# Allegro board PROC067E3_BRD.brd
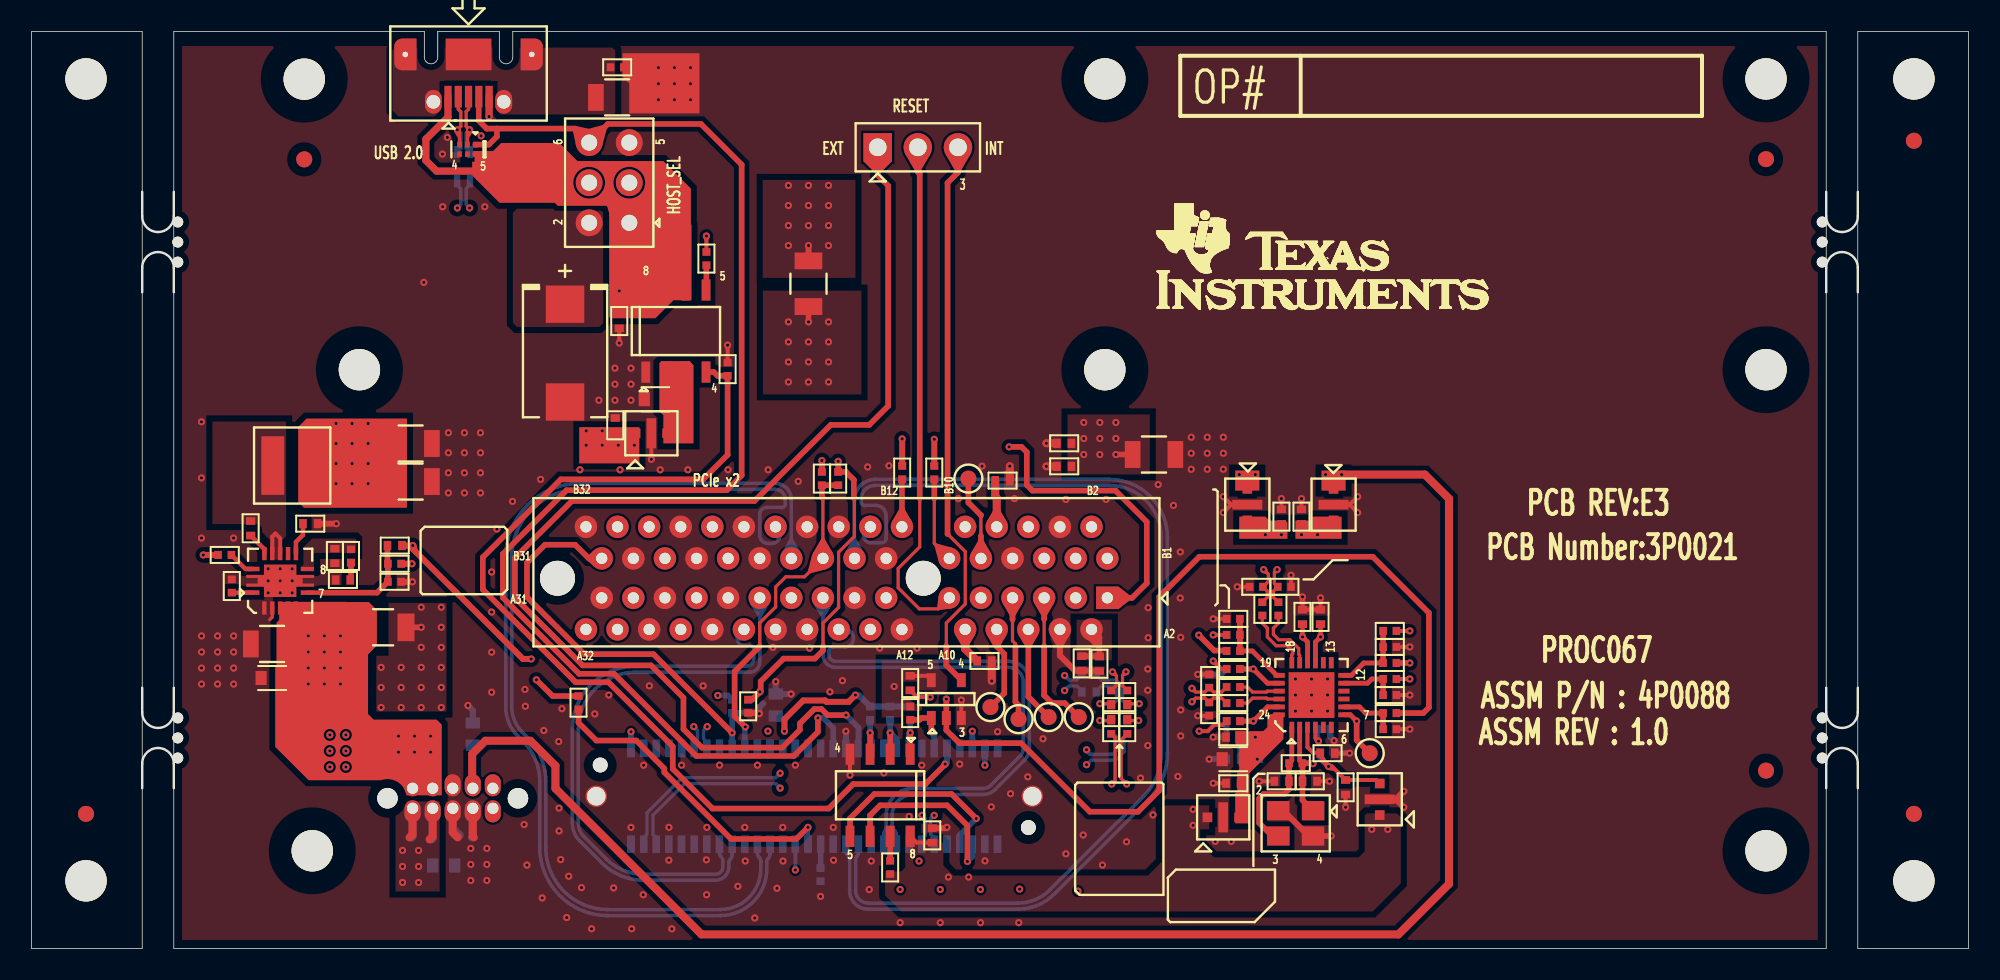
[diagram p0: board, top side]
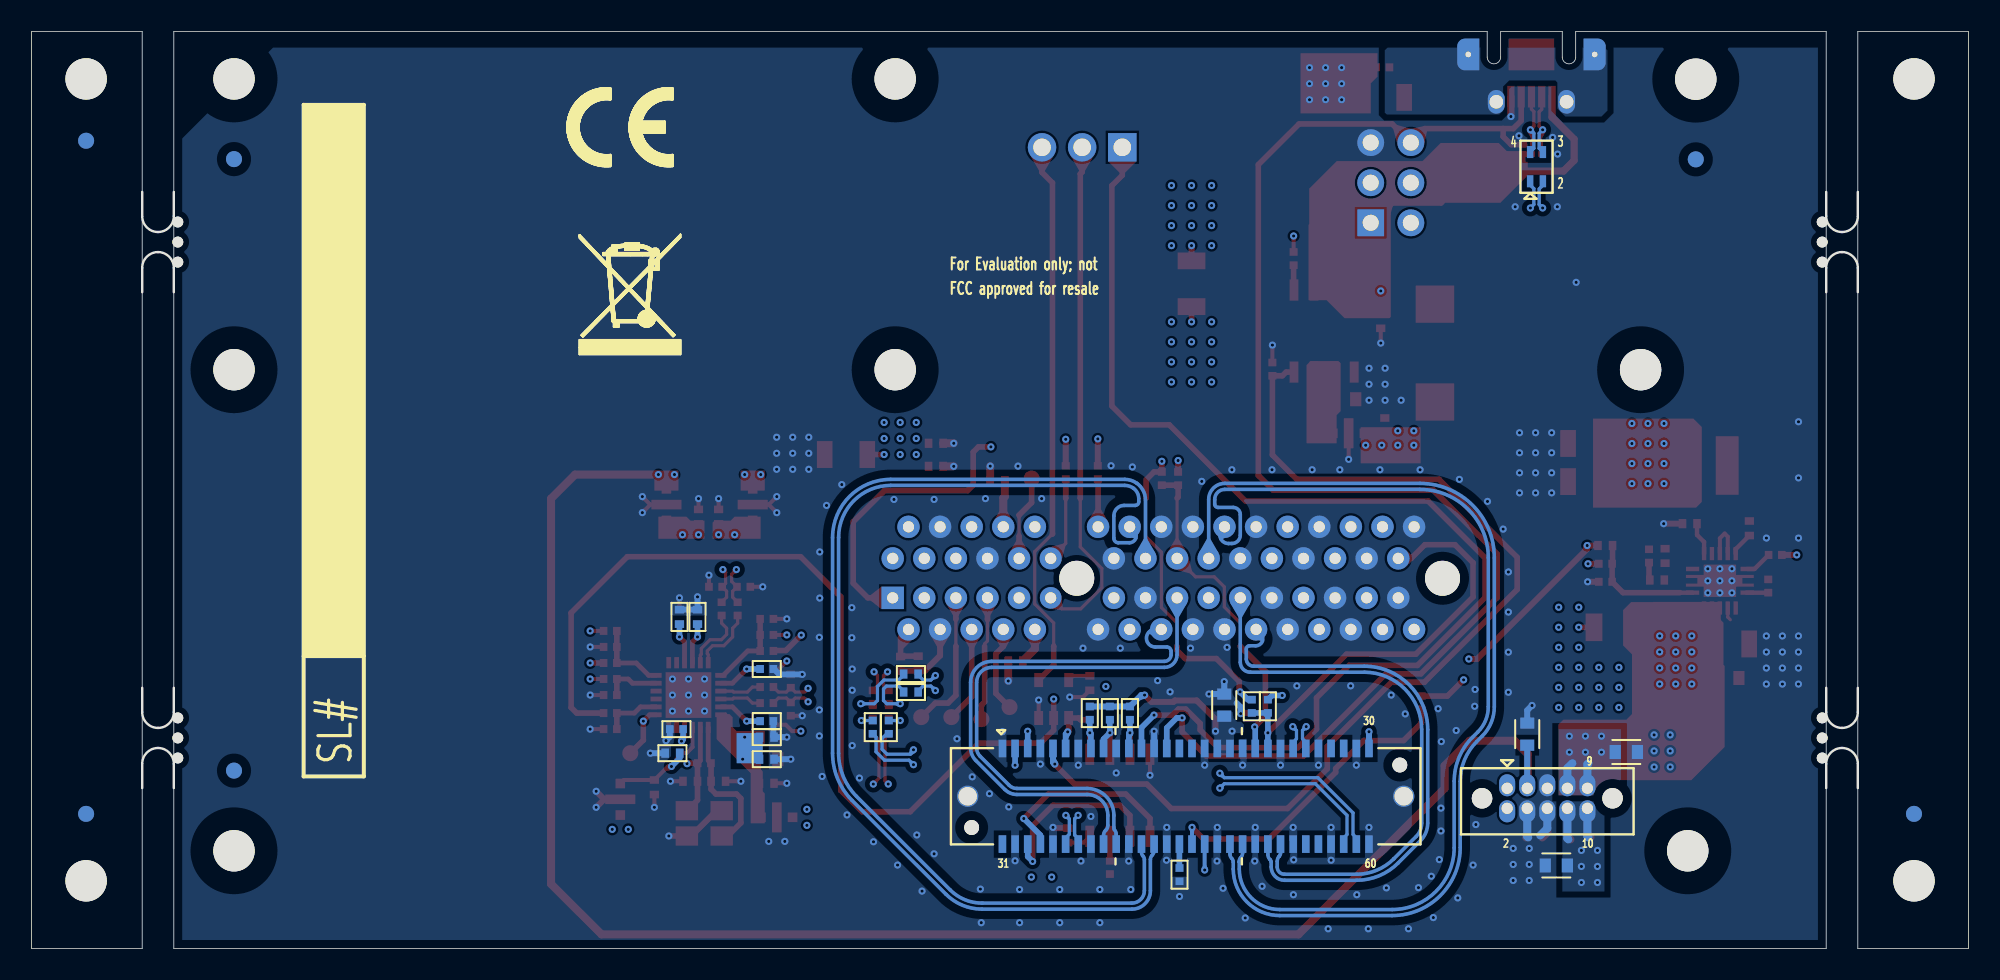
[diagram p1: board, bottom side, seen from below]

Outline 122.58 x 58.09 mm; copper layers: TOP, L02_GND1, L03_PWR, L04_SIG1, L05_GND2, BOTTOM. Coordinates in mm from the lower left corner of the outline.
Outline path: 0,58.09 7,58.09 7,0 0,0 0,58.09 ; 9,58.09 9,0 113.58,0 113.58,58.09 30.46,58.09 30.46,56.47 arc(30.03,56.05) 29.61,56.47 29.61,58.09 25.71,58.09 25.71,56.47 arc(25.28,56.05) 24.86,56.47 24.86,58.09 9,58.09 ; 115.58,58.09 122.58,58.09 122.58,0 115.58,0 115.58,58.09

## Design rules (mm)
net group 4_REFCLK_OUT0N: nets 4_REFCLK_OUT0N N17084031
net group 4_REFCLK_OUT0P: nets 4_REFCLK_OUT0P N17084018
net group DIFF_4_CLKGEN_REFCLK1: nets 4_CLKGEN_REFCLK1N 4_CLKGEN_REFCLK1P
net group DIFF_4_CLKGEN_REFCLK2: nets 4_CLKGEN_REFCLK2N 4_CLKGEN_REFCLK2P
net group DIFF_4_PCIE_REFCLK: nets 4_PCIE_REFCLK_N 4_PCIE_REFCLK_P
net group DIFF_4_REFCLK_IN0: nets 4_REFCLK_IN0N 4_REFCLK_IN0P
net group DIFF_4_USB_CM_D: nets 4_USB_CM_DM 4_USB_CM_DP
net group DIFF_4_USB_D: nets 4_USB_DM 4_USB_DP
net group DIFF_CDCI4_Y1: nets CDCI4_Y1N CDCI4_Y1P
net group DIFF_CDCI4_Y2: nets CDCI4_Y2N CDCI4_Y2P

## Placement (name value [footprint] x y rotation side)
C127  1000pF  [CAP1206]  37.06 53.92 180 top
C128  4.7uF  [CAP0402_0-75]  37.19 39.75 270 top
C129  150uF_10V  [CAPT7343D_3-25]  33.76 37.72 270 top
C130  10uF  [CAP0603_1]  39.48 34.8 180 top
C131  0.1uF  [CAP0402_0-75]  36.94 33.15 90 top
C132  0.01uF  [CAP0402]  65.35 32 180 top
C133  47uF  [CAP1206_2]  23.99 31.99 0 top
C134  47uF  [CAP1206_2]  71.04 31.29 0 top
C135  0.1uF  [CAP0402_0-75]  65.36 30.54 180 top
C136  0.1uF  [CAP0402_0-75]  61.45 29.64 0 top
C137  47uF  [CAP1206_2]  23.99 29.58 0 top
C138  4.7uF  [CAP0402_0-75]  79.1 27.36 90 top
C139  4.7uF  [CAP0402_0-75]  80.37 27.36 90 top
C140  0.01uF  [CAP0402]  17.64 26.91 0 top
C141  0.1uF  [CAP0402_0-75]  13.86 26.62 270 top
C142  510pF  [CAP0402]  22.98 25.53 180 top
C143  91pF  [CAP0402]  19.2 24.87 270 top
C144  1500pF  [CAP0402]  19.71 23.34 180 top
C145  0.1uF  [CAP0402_0-75]  80.44 21.01 270 top
C146  0.1uF  [CAP0402_0-75]  81.58 21.01 270 top
C147  4.7uF  [CAP1206]  15.22 19.29 180 top
C148  0.01uF  [CAP0402]  60.31 18.21 0 top
C149  0.01uF  [CAP0402]  66.47 18.06 270 top
C150  10uF  [CAP0603_1]  15.22 17.13 180 top
C151  0.1uF  [CAP0402_0-75]  55.61 16.81 270 top
C152  0.1uF  [CAP0402_0-75]  67.59 18.03 270 top
C153  0.1uF  [CAP0402_0-75]  76.06 13.39 0 top
C154  0.1uF  [CAP0402_0-75]  82.02 12.37 180 top
C155  10uF  [CAP0603_1]  76.06 11.99 180 top
C156  27pF  [CAP0402]  79.12 10.59 0 top
C157  27pF  [CAP0402]  80.9 10.59 180 top
C158  4.7uF  [CAP0402_0-75]  76.06 10.46 180 top
C159  0.47uF  [CAP0402_0-75]  83.17 10.21 270 top
C160  0.1uF  [CAP0402_0-75]  57.01 7.16 90 top
C221  0.47uF  [CAP0402_0-75]  81.58 21.01 90 bottom
C222  0.47uF  [CAP0402_0-75]  80.44 21.01 90 bottom
C223  0.1uF  [CAP0402_0-75]  66.93 17.39 180 bottom
C224  0.1uF  [CAP0402_0-75]  66.93 16.24 180 bottom
C225  10uF  [CAP0603_1]  47.1 15.42 90 bottom
C226  10uF  [CAP0603_1]  27.92 13.58 90 bottom
C227  0.47uF  [CAP0402_0-75]  76.06 13.39 180 bottom
C228  10uF  [CAP0603_1]  21.65 12.45 180 bottom
C229  4.7uF  [CAP0402_0-75]  82.02 12.37 0 bottom
C230  1uF  [CAP0402]  76.06 11.99 0 bottom
C231  10uF  [CAP0603_1]  26.08 5.26 0 bottom
FL16  4.7uF  [EMIFIL_NFM21P_0805_1]  39.23 32.64 0 top
FL17  0.47uF  [EMIFIL_NFM21P_0805]  76.94 28.12 270 top
FL18  0.47uF  [EMIFIL_NFM21P_0805]  82.41 28.12 270 top
FL19  0.47uF  [EMIFIL_NFM21P_0805]  85.33 9.45 90 top
FL20  0.47uF  [EMIFIL_NFM21P_0805]  75.42 8.31 0 top
FL25  90E  [IND4_ACM2012_90X50_SMD]  27.34 49.53 90 bottom
J5  HDR_2X3  [HDR_2X3_TSW-103-07-D_S_T_8-4]  37.83 45.97 90 top
J13  CON_MUSB-AB_5_F  [CON_USBAB5_475900001_S_R_S_3-1]  27.66 56 180 top
J14  HDR_1X3  [HDR_3X1_100_S_T]  53.55 50.76 180 top
J15  CON_MINIPCI_2X32  [CON_MINIPCI2X32_PCIE-064-02_S_S_T_11]  68.08 22.21 180 top
J22  CON_BTOB_2X30_171450_F  [CON_BTOB2X30_171450_S_S_S_4-6]  49.54 9.64 180 bottom
J23  RECP_2X5  [RECPT_2X5_SFC-105-T1-D-A_S_T_4-6]  29.19 10.15 180 bottom
L3  1uH  [IND_XFL4020_170X170_SMD_2-1]  16.49 30.59 0 top
NOREF  -  [unnamed]  17.25 55.07 0 top
NOREF#2  -  [#2]  122.58 0 90 top
NOREF#3  -  [unnamed#3]  114.58 44.75 90 top
NOREF#4  -  [unnamed]  67.93 36.67 0 top
NOREF#5  -  [unnamed]  119.14 4.28 0 top
NOREF#6  -  [unnamed]  3.44 8.52 0 top
NOREF#7  -  [#2]  7 58.09 0 top
NOREF#8  -  [unnamed]  109.77 55.09 0 top
NOREF#9  -  [#2]  86.93 38.98 0 top
NOREF#10  -  [#2]  0 58.09 0 top
NOREF#11  -  [unnamed#3]  8 44.75 270 top
NOREF#12  -  [unnamed]  3.44 4.28 0 top
NOREF#13  -  [#2]  115.58 58.09 0 top
NOREF#14  -  [#2]  63.38 51.68 0 top
NOREF#15  -  [unnamed]  119.14 51.17 0 top
NOREF#16  -  [unnamed]  109.77 6.19 0 top
NOREF#17  -  [unnamed]  109.77 11.27 0 top
NOREF#18  -  [#2]  -16.96 -24.57 0 top
NOREF#19  -  [unnamed]  119.14 55.09 0 top
NOREF#20  -  [#2]  -2.2 -4.94 0 top
NOREF#21  -  [unnamed]  17.76 6.19 0 top
NOREF#22  -  [unnamed]  3.44 55.09 0 top
NOREF#23  -  [#2]  -267.58 -119.24 0 top
NOREF#24  -  [#2]  90.84 34.74 0 top
NOREF#25  -  [unnamed]  17.25 49.99 0 top
NOREF#26  -  [unnamed]  20.75 36.67 0 top
NOREF#27  -  [unnamed]  109.77 50.01 0 top
NOREF#28  -  [#2]  0 0 0 top
NOREF#29  -  [unnamed#3]  114.58 13.34 90 top
NOREF#30  -  [unnamed]  119.14 8.52 0 top
NOREF#31  -  [unnamed]  67.93 55.09 0 top
NOREF#32  -  [unnamed#3]  8 13.34 270 top
NOREF#33  -  [unnamed]  109.77 36.67 0 top
NOREF#34  -  [unnamed]  3.44 8.52 180 bottom
NOREF#35  -  [#2]  86.17 52.04 180 bottom
NOREF#36  -  [#2]  105.37 10.9 90 bottom
NOREF#37  -  [unnamed]  109.77 50.01 180 bottom
NOREF#38  -  [unnamed]  119.14 51.17 180 bottom
NOREF#39  -  [unnamed]  109.77 11.27 180 bottom
NOREF#40  -  [unnamed]  119.14 8.52 180 bottom
NOREF#41  -  [unnamed]  17.25 49.99 180 bottom
R211  1M_1%  [RES0402]  37.06 55.82 180 top
R212  10K_1%  [RES0402_0-5]  42.71 43.71 270 top
R213  0E_1%  [RES1206]  49.17 42.11 270 top
R214  10K_1%  [RES0402_0-5]  44.05 36.7 90 top
R215  10K_1%  [RES0402_0-5]  50.02 29.77 270 top
R216  0E  [RES0402_0-5]  51.05 29.77 90 top
R217  10K_1%  [RES0402_0-5]  55.1 30.15 270 top
R218  10K_1%  [RES0402_0-5]  57.13 30.15 270 top
R219  100K  [RES0402_0-5]  12.23 24.93 0 top
R220  1.96K_1%  [RES0402]  20.21 24.87 270 top
R221  10K_1%  [RES0402_0-5]  22.97 24.37 0 top
R222  2.2K  [RES0402_0-5]  22.97 23.23 0 top
R223  34K_1%  [RES0402]  12.67 22.96 90 top
R224  49.9E_1%  [RES0402_0-5]  77.52 22.91 180 top
R225  49.9E_1%  [RES0402_0-5]  79.29 22.91 0 top
R226  33E_1%  [RES0402_0-5]  77.9 21.51 90 top
R227  33E_1%  [RES0402_0-5]  78.91 21.51 90 top
R228  4.7K  [RES0402]  76.06 20.88 180 top
R229  0E_1%  [RES1206]  22.25 20.35 0 top
R230  4.7K  [RES0402]  85.96 20.12 180 top
R231  4.7K  [RES0402]  76.06 19.86 0 top
R232  4.7K  [RES0402]  85.96 19.1 0 top
R233  0E  [RES0402_0-5]  76.06 18.85 0 top
R234  0E  [RES0402_0-5]  85.96 18.08 180 top
R235  4.7K  [RES0402]  76.06 17.7 0 top
R236  4.7K  [RES0402]  85.96 17.07 180 top
R237  49.9E_1%  [RES0402_0-5]  74.53 16.94 90 top
R238  33E_1%  [RES0402_0-5]  76.06 16.56 180 top
R239  4.7K  [RES0402]  85.96 16.05 0 top
R240  0E  [RES0402_0-5]  68.33 15.92 90 top
R241  0E  [RES0402_0-5]  69.35 15.92 90 top
R242  33E_1%  [RES0402_0-5]  76.06 15.54 180 top
R243  0E  [RES0402_0-5]  45.35 15.34 90 top
R244  49.9E_1%  [RES0402_0-5]  74.53 15.16 270 top
R245  0E  [RES0402_0-5]  68.33 14.97 270 top
R246  0E  [RES0402_0-5]  69.35 14.97 270 top
R247  10K_1%  [RES0402_0-5]  55.61 14.91 90 top
R248  0E  [RES0402_0-5]  85.96 14.91 180 top
R250  1K  [RES0402_0-5]  76.06 14.4 0 top
R251  0E  [RES0402_0-5]  68.33 14.02 270 top
R252  0E  [RES0402_0-5]  69.35 14.02 270 top
R253  4.7K  [RES0402]  85.96 13.89 0 top
R254  1M_1%  [RES0402]  80.01 11.73 0 top
R255  10K_1%  [RES0402_0-5]  54.34 5.13 90 top
R297  4.7K  [RES0402]  76.06 17.7 180 bottom
R298  0E  [RES0402_0-5]  45.35 15.34 90 bottom
R299  10K_1%  [RES0402_0-5]  44.34 15.34 270 bottom
R300  10K_1%  [RES0402_0-5]  55.61 14.91 270 bottom
R301  10K_1%  [RES0402_0-5]  54.34 14.91 270 bottom
R302  10K_1%  [RES0402_0-5]  53.07 14.91 270 bottom
R304  1K  [RES0402_0-5]  76.06 14.4 180 bottom
R305  0E  [RES0402_0-5]  69.35 14.02 270 bottom
R306  0E  [RES0402_0-5]  68.33 14.02 270 bottom
R307  4.7K  [RES0402]  81.77 13.89 0 bottom
R308  0E  [RES0402_0-5]  49.93 4.67 270 bottom
R311  0E  [RES0402_0-5]  34.62 15.57 90 top
TP22  -  [TP40_SMD]  59.29 29.77 0 top
TP23  -  [TP40_SMD]  60.69 15.29 0 top
TP24  -  [TP40_SMD]  64.37 14.66 0 top
TP25  -  [TP40_SMD]  66.28 14.66 0 top
TP26  -  [TP40_SMD]  62.47 14.53 0 top
TP27  -  [TP40_SMD]  84.69 12.37 270 top
U20  TPD4S012DRYR  [SON6_19-68_40X60_PB_0-6]  27.59 50.63 270 top
U21  TPS2051BD  [SOIC8_1-8]  40.78 39.12 90 top
U22  TPS54821RHLT  [QFN14_19-68_145X145]  15.73 23.29 0 top
U23  CDCI6214RGET  [QFN24_19-68_160X160_1]  81.01 16.05 90 top
U24  SN74LVC1G08DBVRE4  [SOT23-5]  57.89 15.8 90 top
U25  CAT24C256WI-GT3  [SOIC8_1-8]  53.7 9.7 270 top
Y6  25.000MHz  [XTAL4_NX3225GA_130X100_SMD]  80.01 7.92 180 top

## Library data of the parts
C127 C128 C130-C160 C221 C222 C225-C231 = CAP
C129 = CAP_POL
C223 C224 = CAP: signal model: cap
FL16 = EMI_FILTER
FL17-FL20 = CAP_FILTER
FL25 = EMIFILTER_ACM
J5 = HEADER_3X2
J13 = CON_USB_MINI-AB_10
J14 = HEADER_3X1
J15 = CON_MINIPCI_32X2
J22 = CON_BTOB_30X2_171450
J23 = RECP_5X2
L3 = INDUCTOR
R211-R248 R250-R255 R297-R302 R304-R308 R311 = RESISTOR
TP22-TP27 = TESTPOINT
U20 = TPD4S012DRY_SON6
U21 = TPS2051BD_SOIC8
U22 = TPS54620_QFN14
U23 = CDCI6214RGET_VQFN24
U24 = SN74LVC1G08DBVRE4_SOT23-5
U25 = CAT24C256WI-GT3_SOIC8
Y6 = CRY_CX3225GB

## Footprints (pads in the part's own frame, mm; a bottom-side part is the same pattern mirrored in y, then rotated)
CAP0402
  rect 0.483x0.584 smd: 1(-0.46,0) 2(0.46,0)
CAP0402_0-75
  rect 0.483x0.584 smd: 1(-0.46,0) 2(0.46,0)
CAP0603_1
  rect 0.711x0.889 smd: 1(-0.7,0) 2(0.7,0)
CAP1206
  rect 0.991x1.702 smd: 1(-1.35,0) 2(1.35,0)
CAP1206_2
  rect 0.991x1.702 smd: 1(-1.35,0) 2(1.35,0)
CAPT7343D_3-25
  rect 2.362x2.438 smd: 1(-3.1,0) 2(3.1,0)
CON_BTOB2X30_171450_S_S_S_4-6
  round 0.94 hole 1.067 unplated: (-13.55,-1.98) (13.55,1.98)
  rect 0.483x1.118 smd: 1(-11.6,3.03) 2(-10.8,3.03) 3(-10,3.03) 4(-9.2,3.03) 5(-8.4,3.03) 6(-7.6,3.03) 7(-6.8,3.03) 8(-6,3.03) 9(-5.2,3.03) 10(-4.4,3.03) 11(-3.6,3.03) 12(-2.8,3.03) 13(-2,3.03) 14(-1.2,3.03) 15(-0.4,3.03) 16(0.4,3.03) 17(1.2,3.03) 18(2,3.03) 19(2.8,3.03) 20(3.6,3.03) 21(4.4,3.03) 22(5.2,3.03) 23(6,3.03) 24(6.8,3.03) 25(7.6,3.03) 26(8.4,3.03) 27(9.2,3.03) 28(10,3.03) 29(10.8,3.03) 30(11.6,3.03) 31(-11.6,-3.03) 32(-10.8,-3.03) 33(-10,-3.03) 34(-9.2,-3.03) 35(-8.4,-3.03) 36(-7.6,-3.03) 37(-6.8,-3.03) 38(-6,-3.03) 39(-5.2,-3.03) 40(-4.4,-3.03) 41(-3.6,-3.03) 42(-2.8,-3.03) 43(-2,-3.03) 44(-1.2,-3.03) 45(-0.4,-3.03) 46(0.4,-3.03) 47(1.2,-3.03) 48(2,-3.03) 49(2.8,-3.03) 50(3.6,-3.03) 51(4.4,-3.03) 52(5.2,-3.03) 53(6,-3.03) 54(6.8,-3.03) 55(7.6,-3.03) 56(8.4,-3.03) 57(9.2,-3.03) 58(10,-3.03) 59(10.8,-3.03) 60(11.6,-3.03)
  round 1.346 hole 1.168: SH1(-13.8,0) SH2(13.8,0)
CON_MINIPCI2X32_PCIE-064-02_S_S_T_11
  round 2.21 hole 2.337 unplated: (11.65,-1.24) (34.8,-1.24)
  rect 1.422x1.422 hole 0.711: A1(0,0)
  round 1.422 hole 0.711: A2(1,2) A3(2,0) A4(3,2) A5(4,0) A6(5,2) A7(6,0) A8(7,2) A9(8,0) A10(9,2) A12(13,2) A13(14,0) A14(15,2) A15(16,0) A16(17,2) A17(18,0) A18(19,2) A19(20,0) A20(21,2) A21(22,0) A22(23,2) A23(24,0) A24(25,2) A25(26,0) A26(27,2) A27(28,0) A28(29,2) A29(30,0) A30(31,2) A31(32,0) A32(33,2) B1(0,-2.5) B2(1,-4.5) B3(2,-2.5) B4(3,-4.5) B5(4,-2.5) B6(5,-4.5) B7(6,-2.5) B8(7,-4.5) B9(8,-2.5) B10(9,-4.5) B12(13,-4.5) B13(14,-2.5) B14(15,-4.5) B15(16,-2.5) B16(17,-4.5) B17(18,-2.5) B18(19,-4.5) B19(20,-2.5) B20(21,-4.5) B21(22,-2.5) B22(23,-4.5) B23(24,-2.5) B24(25,-4.5) B25(26,-2.5) B26(27,-4.5) B27(28,-2.5) B28(29,-4.5) B29(30,-2.5) B30(31,-4.5) B31(32,-2.5) B32(33,-4.5)
  round 1.372 hole 0.711: A11(10,0)
  round 1.397 hole 0.711: B11(10,-2.5)
CON_USBAB5_475900001_S_R_S_3-1
  rect 0.457x1.372 smd: 1(1.3,2.04) 2(0.65,2.04) 3(0,2.04) 4(-0.65,2.04) 5(-1.3,2.04)
  oval 1.067x1.499 hole 0.864: 6(2.225,2.365) 7(-2.225,2.365)
  custom 0.35x0.35 hole 0.813x1.626: 8(-4,-0.635) 9(4,-0.635)
  rect 2.896x2.007 smd: 10(0,-0.635)
EMIFIL_NFM21P_0805
  rect 0.61x0.61 smd: 1(-1,0) 3(1,0)
  rect 0.61x1.905 smd: 2(0,0)
EMIFIL_NFM21P_0805_1
  rect 0.61x0.61 smd: 1(-1,0) 3(1,0)
  rect 0.61x1.905 smd: 2(0,0)
HDR_2X3_TSW-103-07-D_S_T_8-4
  rect 1.702x1.702 hole 1.016: 1(0,0)
  round 1.702 hole 1.016: 2(0,2.54) 3(2.54,0) 4(2.54,2.54) 5(5.08,0) 6(5.08,2.54)
HDR_3X1_100_S_T
  rect 1.803x1.803 hole 1.118: 1(0,0)
  round 1.803 hole 1.118: 2(-2.54,0) 3(-5.08,0)
IND4_ACM2012_90X50_SMD
  rect 0.762x0.406 smd: 1(-0.925,0.403) 2(-0.925,-0.403) 3(0.925,-0.403) 4(0.925,0.403)
IND_XFL4020_170X170_SMD_2-1
  rect 1.448x3.708 smd: 1(-1.225,0) 2(1.225,0)
QFN14_19-68_145X145
  rect 0.838x0.279 smd: 1(-1.725,-0.75) 7(1.725,-0.75) 8(1.725,0.75) 14(-1.725,0.75)
  rect 0.279x0.838 smd: 2(-1,-1.725) 3(-0.5,-1.725) 4(0,-1.725) 5(0.5,-1.725) 6(1,-1.725) 9(1,1.725) 10(0.5,1.725) 11(0,1.725) 12(-0.5,1.725) 13(-1,1.725)
  custom 0.512x0.512 smd: 15(0,0)
QFN24_19-68_160X160_1
  rect 0.711x0.305 smd: 1(-2.05,1.25) 2(-2.05,0.75) 3(-2.05,0.25) 4(-2.05,-0.25) 5(-2.05,-0.75) 6(-2.05,-1.25) 13(2.05,-1.25) 14(2.05,-0.75) 15(2.05,-0.25) 16(2.05,0.25) 17(2.05,0.75) 18(2.05,1.25)
  rect 0.305x0.711 smd: 7(-1.25,-2.05) 8(-0.75,-2.05) 9(-0.25,-2.05) 10(0.25,-2.05) 11(0.75,-2.05) 12(1.25,-2.05) 19(1.25,2.05) 20(0.75,2.05) 21(0.25,2.05) 22(-0.25,2.05) 23(-0.75,2.05) 24(-1.25,2.05)
  rect 2.896x2.896 smd: 25(0,0)
RECPT_2X5_SFC-105-T1-D-A_S_T_4-6
  round 1.295 hole 1.422 unplated: (-1.59,-0.635) (6.67,-0.635)
  oval 1.016x1.397 hole 0.711: 1(0,0) 2(0,-1.27) 3(1.27,0) 4(1.27,-1.27) 5(2.54,0) 6(2.54,-1.27) 7(3.81,0) 8(3.81,-1.27) 9(5.08,0) 10(5.08,-1.27)
RES0402
  rect 0.483x0.508 smd: 1(-0.42,0) 2(0.42,0)
RES0402_0-5
  rect 0.483x0.508 smd: 1(-0.42,0) 2(0.42,0)
RES1206
  rect 1.067x1.753 smd: 1(-1.45,0) 2(1.45,0)
SOIC8_1-8
  rect 1.346x0.559 smd: 1(-2.6,1.905) 2(-2.6,0.635) 3(-2.6,-0.635) 4(-2.6,-1.905) 5(2.6,-1.905) 6(2.6,-0.635) 7(2.6,0.635) 8(2.6,1.905)
SON6_19-68_40X60_PB_0-6
  rect 0.356x0.305 smd: 1(-0.3,0.5) 2(-0.3,0) 3(-0.3,-0.5) 4(0.3,-0.5) 5(0.3,0) 6(0.3,0.5)
SOT23-5
  rect 0.889x0.559 smd: 1(-1.2,0.95) 2(-1.2,0) 3(-1.2,-0.95) 4(1.2,-0.95) 5(1.2,0.95)
TP40_SMD
  round 1.016 smd: 1(0,0)
unnamed
  round 2.616 hole 2.743 unplated: (0,0)
unnamed#3
  round 0.686 hole 0.813 unplated: (-1.27,1.254) (0,1.254) (1.27,1.254)
XTAL4_NX3225GA_130X100_SMD
  rect 1.422x1.219 smd: 1(-1.1,-0.8) 2(1.1,-0.8) 3(1.1,0.8) 4(-1.1,0.8)

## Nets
DGND4: C127.1 C128.2 C129.2 C130.2 C131.2 C132.2 C133.2 C134.2 C135.2 C136.2 C137.2 C138.2 C139.2 C140.2 C143.2 C144.2 C145.1 C146.1 C147.2 C148.2 C149.2 C150.2 C151.2 C152.2 C153.1 C154.1 C155.2 C156.1 C157.1 C158.2 C159.2 C160.2 C221.2 C222.2 C225.2 C226.2 C227.2 C228.2 C229.2 C230.1 C231.2 FL16.2(GND) FL17.2(GND1) FL18.2(GND1) FL19.2(GND1) FL20.2(GND1) J5.5 J13.5(GND) J15.A4(GND#A4) J15.A12(GND#A12) J15.A15(GND#A15) J15.A18(GND#A18) J15.A20(GND#A20) J15.A23(GND#A23) J15.A24(GND#A24) J15.A27(GND#A27) J15.A28(GND#A28) J15.A31(GND#A31) J15.B4(GND#B4) J15.B7(GND#B7) J15.B13(GND#B13) J15.B16(GND#B16) J15.B18(GND#B18) J15.B21(GND#B21) J15.B22(GND#B22) J15.B25(GND#B25) J15.B26(GND#B26) J15.B29(GND#B29) J15.B32(GND#B32) J22.1 J22.4 J22.7 J22.10 J22.13 J22.17 J22.20 J22.23 J22.26 J22.29 J22.32 J22.35 J22.38 J22.41 J22.44 J22.48 J22.51 J22.54 J22.57 J22.60 J22.SH1 J22.SH2 J23.4 J23.5 J23.6 R211.1 R214.2 R222.2 R223.2 R224.2 R225.2 R228.2 R232.2 R237.2 R239.2 R243.1 R244.2 R253.2 R297.2 R304.2 R307.2 R308.2 U20.4(GND) U21.1(GND) U22.2(GND1) U22.3(GND2) U22.15(PAD) U23.25(GND) U24.3(GND) U25.4(VSS) Y6.2(NC1) Y6.4(NC2)
V3V3_REF_CDCI4: C154.2 C159.1 C229.1 FL19.3(OUT) U23.3(VDDREF)
V3V3_VCO_CDCI4: C153.2 C155.1 C158.1 C227.1 C230.2 FL20.3(OUT) U23.24(VDDVCO)
VDD12_CDCI4: C138.1 C145.2 C222.1 FL17.3(OUT) U23.16(VDDO12)
VDD34_CDCI4: C139.1 C146.2 C221.1 FL18.3(OUT) U23.15(VDDO34)
4_BOARDID_A0: J22.8 R300.2 U25.1(A0)
4_BOARDID_A1: J22.9 R301.2 U25.2(A1)
4_BOARDID_A2: J22.11 R302.2 U25.3(A2)
4_BRD_DET: J22.45 R308.1
4_CLKGEN_REFCLK1N: R237.1 R238.2 R240.2
4_CLKGEN_REFCLK1P: R241.2 R242.2 R244.1
4_CLKGEN_REFCLK2N: R225.1 R227.2 R251.2
4_CLKGEN_REFCLK2P: R224.1 R226.2 R252.2
4_EEPROM_WP: R255.2 U25.7(WP)
4_MCU_SCL: J15.B5(SMCLK) J22.2 R234.1
4_MCU_SDA: J15.B6(SMDAT) J22.3 R233.1
4_PCIE_CLKREQN: J15.B12(RSVD4) R217.2
4_PCIE_PRSNT1N: J15.A1(PRSNT1#) R216.2 R243.2 R298.2
4_PCIE_PRSNTA2N: J15.B17(PRSNT2#_1) J22.21 R215.2 R216.1
4_PCIE_PRSNTB2N: J15.B31(PRSNT2#_2) J22.22 R298.1 R299.2
4_PCIE_REFCLK_N: J15.A14(REFCLK-) R245.2 R251.1 R306.1
4_PCIE_REFCLK_P: J15.A13(REFCLK+) R246.2 R252.1 R305.1
4_PCIE_RESETN: J14.2 J15.A11(PERST#)
4_PCIE_RST: J22.6 R247.1 U24.1(A)
4_PCIE_RXN0: J15.A17(PERN0) J22.40
4_PCIE_RXN1: J15.A22(PERN1) J22.52
4_PCIE_RXP0: J15.A16(PERP0) J22.39
4_PCIE_RXP1: J15.A21(PERP1) J22.53
4_PCIE_TCK: J15.A5(JTAG2) TP25.1(TP)
4_PCIE_TDI: J15.A6(JTAG3) TP24.1(TP)
4_PCIE_TDO: J15.A7(JTAG4) TP26.1(TP)
4_PCIE_TMS: J15.A8(JTAG5) TP23.1(TP)
4_PCIE_TRSTN: J15.B9(JTAG1) TP22.1(TP)
4_PCIE_TXN0: J15.B15(PETN0) J22.43
4_PCIE_TXN1: J15.B20(PETN1) J22.50
4_PCIE_TXP0: J15.B14(PETP0) J22.42
4_PCIE_TXP1: J15.B19(PETP1) J22.49
4_PCIE_WAKEN: J15.B11(WAKE#) R218.2 R311.2
4_PCIE_WAKEN_3V3: J22.46 R311.1
4_PORZ: J14.1 J22.12
4_PORZ_OUT: J22.30 R248.1 U24.2(B)
4_REFCLK_IN0N: J22.58 R306.2
4_REFCLK_IN0P: J22.59 R305.2
4_REFCLK_OUT0N: C224.2 J22.24
4_REFCLK_OUT0P: C223.2 J22.25
4_RESETN: J14.3 U24.4(Y)
4_USB_CM_DM: FL25.3 J13.2(D-) U20.3(ID)
4_USB_CM_DP: FL25.4 J13.3(D+) U20.2(D-)
4_USB_DM: FL25.2 J22.36
4_USB_DP: FL25.1 J22.37
4_USB_DRV_VBUS: J22.5 R214.1 U21.4(EN)
4_USB_ID: J5.6 J13.4(ID) J22.14 U20.1(D+)
4_USB_VBUS: C128.1 J5.1 J13.1(VCC) J22.47 U20.6(VBUS) U21.6(OUT1) U21.7(OUT2) U21.8(OUT3)
4_VCC_1V8: C226.1 FL17.1(IN) FL18.1(IN) J23.3
4_VCC_3V3: C133.1 C137.1 C142.1 C151.1 L3.2 R213.1 R219.1 R221.2 R247.2 U24.5(VCC)
4_VCC_5V: C131.1 C231.1 FL16.1(I) J23.8 J23.10 R212.1
4_VCC_12V: C147.1 C150.1 C228.1 J23.7 J23.9 R229.1 U22.4(PVIN1) U22.5(PVIN2) U22.6(VIN)
4_VCC_FUN_3V3: C160.1 C225.1 FL19.1(IN) FL20.1(IN) J22.18 J22.19 R230.1 R231.1 R235.1 R236.1 R250.1 R255.1 R300.1 R301.1 R302.1 U25.8(VCC)
4_VCC_PCIE_3V3: C136.1 C148.1 J15.A9(+3.3V#A9) J15.A10(+3.3V#A10) J15.B8(+3.3V#B8) J15.B10(3.3VAUX) R213.2 R215.1 R217.1 R218.1 R299.1
4_VCC_PCIE_12V: C132.1 C134.1 C135.1 C149.1 C152.1 J15.A2(+12V#A2) J15.A3(+12V#A3) J15.B1(+12V#B1) J15.B2(+12V#B2) J15.B3(+12V#B3) R229.2
4_WKUP_SCL: J22.33 U25.6(SCL)
4_WKUP_SDA: J22.34 U25.5(SDA)
CDCI4_EEPROMSEL: R250.2 R304.1 U23.23(EEPROMSEL)
CDCI4_OE1: R235.2 R297.1 U23.20(STATUS/GPIO1)
CDCI4_OE2: R228.1 R231.2 R233.2 U23.19(SDA/GPIO2)
CDCI4_OE3: R230.2 R232.1 R234.2 U23.12(SCL/GPIO3)
CDCI4_OE4: R236.2 R239.1 U23.11(OE/GPIO4)
CDCI4_REFSEL: R307.1 U23.4(REFSEL)
CDCI4_RST: R248.2 R253.1 U23.8(RESETN/SYNC)
CDCI4_XIN: C156.2 R254.1 U23.1(XIN) Y6.3(HOT2)
CDCI4_XOUT: C157.2 R254.2 TP27.1(TP) U23.2(XOUT) U23.7(Y0) Y6.1(HOT1)
CDCI4_Y1N: R238.1 U23.21(Y1N)
CDCI4_Y1P: R242.1 U23.22(Y1P)
CDCI4_Y2N: R227.1 U23.17(Y2N)
CDCI4_Y2P: R226.1 U23.18(Y2P)
PWR_GOOD4: R219.2 U22.14(PWRGD)
USB_SHIELD4: C127.2 J13.6(SH1) J13.7(SH2) J13.8(SH3) J13.9(SH4) J13.10(SH5) R211.2
N16880317: C130.1 FL16.3(O) U21.2(IN1) U21.3(IN2)
N16880346: R212.2 U21.5(O\C\)
N17084018: C223.1 R241.1 R246.1
N17084031: C224.1 R240.1 R245.1
N17117472: C142.2 R221.1 R222.1 U22.7(VSENSE)
N17117476: C141.1 L3.1 U22.11(PH1) U22.12(PH2)
N17117528: C144.1 R220.2
N17117530: C143.1 R220.1 U22.8(COMP)
N17117540: R223.1 U22.1(RT/CLK)
N17117546: C140.1 U22.9(SS/TR)
N17117564: C141.2 U22.13(BOOT)
N17797147: C129.1 J5.2

Pads without a net: J5 3 4; J15 A19 A25 A26 A29 A30 A32 B23 B24 B27 B28 B30; J22 15 16 27 28 31 55 56; J23 1 2; U20 5; U22 10; U23 5 6 9 10 13 14

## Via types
v1: diameter 0.457, hole 0.203, TOP to BOTTOM, 434 vias

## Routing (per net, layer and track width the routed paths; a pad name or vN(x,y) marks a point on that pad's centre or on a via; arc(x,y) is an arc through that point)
DGND4: length 76
  TOP w0.203: U22.3 15.23,20.99 15.07,20.83
  TOP w0.254: v1(75.42,27.61) 75.93,28.12 ; 75.93,28.12 FL17.2 ; 75.93,28.12 v1(75.42,28.63) ; 83.42,28.12 FL18.2 ; 83.42,28.12 v1(83.93,27.61) ; 83.42,28.12 v1(83.93,28.63) ; R225.2 v1(79.71,23.65) ; v1(81.58,22.21) C146.1 C145.1 v1(80.44,22.28) ; R214.2 v1(44.05,38.23) ; R239.2 v1(87.23,16.05) ; R224.2 v1(76.31,22.91) ; C154.1 v1(83.42,12.37) ; C138.2 v1(79.1,28.5) ; C157.1 v1(82.15,10.59) ; U24.3 v1(58.84,15.74) ; R244.2 v1(73.81,14.74) ; R237.2 v1(73.81,17.36) ; C151.2 56.04,15.93 v1(56.88,15.93) ; FL16.2 v1(39.23,30.99) ; U25.4 v1(51.8,10.97) ; C139.2 v1(80.37,28.5) ; R232.2 v1(87.23,19.1) ; C156.1 v1(77.69,10.59) ; C128.2 v1(37.19,38.35) ; C158.2 v1(74.79,10.46) ; R253.2 v1(87.23,13.89) ; C159.2 v1(83.17,8.94) ; R228.2 v1(74.79,20.88)
  TOP w0.356: Y6.4 v1(82.25,7.12)
  TOP w0.381: J15.A4 65.08,18.55 66.04,17.6 C149.2 67.56,17.6 C152.2 ; C160.2 57.89,7.62 v1(57.94,7.67) ; v1(86.85,8.94) 86.34,9.45 ; 86.34,9.45 FL19.2 ; 86.34,9.45 v1(86.85,9.96) ; R222.2 v1(24.1,23.23) ; Y6.2 79.23,8.72 80.83,7.12 Y6.4 ; R243.1 46.01,14.92 v1(46.06,14.87) ; C140.2 v1(19.29,26.91)
  TOP w0.457: J13.5 v1(28.96,52.71)
  TOP w0.508: C132.2 v1(64.22,32) ; 26.97,7.04 26.65,7.35 J23.6 ; J23.4 27.92,7.1 27.99,7.04 ; C136.2 v1(61.91,30.56) ; C148.2 v1(60.77,16.94) ; C135.2 v1(64.22,30.54)
  L02_GND1 w0.508: J23.4 27.92,7.11 28.18,6.85 ; 26.59,6.65 26.65,6.72 J23.6 J23.5 26.65,11.93 26.72,11.99
  BOTTOM w0.381: v1(74.79,13.39) C153.1 75.64,13.43 R304.2 ; v1(73.81,17.36) 75.26,17.36 75.6,17.7 R297.2 ; R307.2 82.19,13.41 v1(82.43,13.17) ; v1(27.62,15.39) 27.92,15.09 C226.2 ; C230.1 v1(74.53,11.99) ; v1(46.06,14.87) 46.06,15.28 46.31,15.54 ; v1(47.1,16.91) C225.2 v1(48.07,16.12) ; v1(80.44,22.28) C145.1 C146.1 ; C154.1 v1(83.42,12.37) ; J22.13 v1(51.54,13.76)
  BOTTOM w0.508: 27.1,7.16 26.65,7.61 J23.6 ; J23.4 27.92,7.1 27.86,7.04
  vias: v1(10.75,33.37) v1(10.75,29.81) v1(10.75,26) v1(10.76,19.8) v1(10.76,18.78) v1(10.76,17.76) v1(10.76,16.75) v1(11.77,19.8) v1(11.77,18.78) v1(11.77,17.76) v1(11.77,16.75) v1(12.78,26) v1(12.79,19.8) v1(12.79,18.78) v1(12.79,17.76) v1(12.79,16.75) v1(14.97,24.05) v1(14.97,23.29) v1(14.97,22.53) v1(15.73,24.05) v1(15.73,23.29) v1(15.73,22.53) v1(16.49,24.05) v1(16.49,23.29) v1(16.49,22.53) v1(18.88,13.53) v1(18.88,12.51) v1(18.88,11.5) v1(19.89,13.53) v1(19.89,12.51) v1(19.89,11.5) v1(24.83,42.2) v1(26,50.33) v1(26.02,46.99) v1(26.31,51.38) v1(26.38,32.67) v1(26.38,31.4) v1(26.38,30.13) v1(26.38,28.86) v1(27.39,32.67) v1(27.39,31.4) v1(27.39,30.13) v1(27.39,28.86) v1(27.8,6.34) v1(27.8,5.32) v1(27.8,4.31) v1(28.45,51.49) v1(28.41,32.67) v1(28.41,31.4) v1(28.41,30.13) v1(28.41,28.86) v1(28.68,46.99) v1(28.81,6.34) v1(28.81,5.32) v1(28.81,4.31) v1(29.12,23.85) v1(29.12,21.31) v1(29.12,18.77) v1(29.12,16.23) v1(29.45,26.57) v1(30.44,28.32) v1(31.22,16.41) v1(31.17,7.85) v1(31.25,15.34) v1(31.35,5.28) v1(32.22,29.72) v1(32.32,3.2) v1(32.42,13.81) v1(33.36,13.11) v1(33.38,8.89) v1(33.38,7.44) v1(33.49,5.63) v1(33.56,15.19) v1(33.87,1.96) v1(33.99,4.57) v1(34.7,30.33) v1(34.81,3.85) v1(35.44,1.24) v1(35.64,14.86) v1(35.9,34.73) v1(36.53,16.05) v1(36.84,3.84) v1(36.92,36.76) v1(36.92,35.75) v1(36.92,34.73) v1(37.24,30.33) v1(37.94,36.76) v1(37.94,35.75) v1(37.94,34.73) v1(37.94,7.67) v1(37.98,1.24) v1(38.74,11.61) v1(38.71,3.4) v1(39.1,16.64) v1(39.67,55.8) v1(39.67,54.79) v1(39.67,53.77) v1(39.78,30.33) v1(40.34,7.67) v1(40.34,5.59) v1(40.52,1.24) v1(40.69,55.8) v1(40.69,54.79) v1(40.69,53.77) v1(41.14,11.61) v1(41.54,30.33) v1(41.7,55.8) v1(41.7,54.79) v1(41.7,53.77) v1(42.5,16.64) v1(42.74,7.67) v1(42.71,5.61) v1(42.72,3.4) v1(43.54,11.61) v1(44.08,30.33) v1(44.7,3.94) v1(45.14,7.67) v1(45.17,5.54) v1(45.77,1.93) v1(45.94,11.61) v1(46.62,30.33) v1(46.92,19.08) v1(47.18,3.81) v1(47.54,7.67) v1(47.56,5.54) v1(48.34,11.61) v1(48.52,29.59) v1(49.23,19.02) v1(49.93,3.29) v1(50.53,16.26) v1(50.74,7.67) v1(50.76,5.59) v1(51.32,16.97) v1(52.92,30.51) v1(53.02,3.73) v1(53.15,5.54) v1(53.68,19.02) v1(53.94,11.12) v1(54.26,30.58) v1(54.97,3.73) v1(54.97,1.63) v1(55.54,8.36) v1(56.04,19.02) v1(56.17,5.54) v1(56.34,11.61) v1(57.51,3.73) v1(57.51,1.63) v1(58.66,28.5) v1(58.74,11.68) v1(60.05,3.73) v1(60.05,1.63) v1(60.16,30.56) v1(60.34,5.55) v1(60.74,8.97) v1(61.14,13.73) v1(61.96,9.8) v1(62.21,28.5) v1(62.53,3.76) v1(62.48,1.63) v1(63.05,10.87) v1(64.02,13.28) v1(65.46,28.45) v1(65.46,5.99) v1(66.23,3.63) v1(66.56,7.19) v1(67.78,5.28) v1(68,28.45) v1(69.3,6.76) v1(70.19,10.79) v1(70.65,17.7) v1(70.65,16.36) v1(70.65,12.85) v1(70.67,21.59) v1(70.67,19.68) v1(70.98,8.46) v1(71.31,29.39) v1(72.27,28.07) v1(72.55,10.9) v1(72.7,25.12) v1(72.7,22.2) v1(72.73,19.71) v1(72.73,15.11) v1(72.73,13.46) v1(73.4,32.39) v1(73.4,31.37) v1(73.4,30.36) v1(74.41,32.39) v1(74.41,31.37) v1(74.41,30.36) v1(74.91,6.78) v1(75.43,32.39) v1(75.43,31.37) v1(75.43,30.36) v1(75.93,6.78) v1(79.99,17.07) v1(79.99,16.05) v1(79.99,15.04) v1(81.01,17.07) v1(81.01,16.05) v1(81.01,15.04) v1(82.02,17.07) v1(82.02,16.05) v1(82.02,15.04)
V3V3_REF_CDCI4: length 8.1
  TOP w0.254: U23.3 80.75,13.99 80.75,12.75 81.11,12.4 81.35,12.4 81.37,12.37 C154.2 81.56,12.18 81.76,11.98 81.76,11.81 82.04,11.53 v1(82.09,11.53) 82.31,11.53 C159.1 85.1,10.67 FL19.3
  BOTTOM w0.356: v1(82.09,11.53) 81.56,12.05 C154.2
V3V3_VCO_CDCI4: length 3.6
  TOP w0.254: C153.2 v1(77.45,13.39) ; U23.24 78.68,14.8 78.41,14.53
  BOTTOM w0.254: C153.2 v1(77.45,13.39) ; C230.2 v1(77.58,11.99)
VDD12_CDCI4: length 12.6
  TOP w0.254: C145.2 v1(80.44,19.74) ; C138.1 v1(79.1,26.21)
  TOP w0.305: U23.16 80.76,19.41 v1(80.44,19.74)
  L04_SIG1 w0.234: v1(80.44,19.74) 81.08,20.38 81.08,24.23 v1(79.1,26.21) v1(78.09,26.21)
  BOTTOM w0.356: C145.2 v1(80.44,19.74)
VDD34_CDCI4: length 12.7
  TOP w0.254: C139.1 v1(80.37,26.21) ; C146.2 v1(81.58,19.74)
  TOP w0.305: v1(81.58,19.74) 81.26,19.41 U23.15
  L04_SIG1 w0.234: v1(80.37,26.21) v1(81.39,26.21) 82.84,24.76 82.84,20.99 v1(81.58,19.74)
  BOTTOM w0.356: C146.2 v1(81.58,19.74)
4_BOARDID_A0: length 3.2
  TOP w0.356: v1(55.61,13.66) U25.1
  BOTTOM w0.356: R300.2 v1(55.61,13.66) 55.54,13.59 J22.8
4_BOARDID_A1: length 3.3
  TOP w0.356: v1(54.34,13.66) U25.2
  BOTTOM w0.356: J22.9 54.74,13.26 v1(54.34,13.66) R301.2
4_BOARDID_A2: length 3.2
  TOP w0.356: v1(53.07,13.66) U25.3
  BOTTOM w0.356: J22.11 53.14,13.59 v1(53.07,13.66) R302.2
4_BRD_DET: length 1.5
  BOTTOM w0.356: R308.1 49.94,5.1 J22.45
4_CLKGEN_REFCLK1N: length 11.7
  TOP w0.203: v1(73.44,16.48) 73.68,16.24 74.25,16.24 R237.1 74.81,16.24 75.32,16.24 R238.2 ; R240.2 68.67,16.68 68.67,17.27 v1(68.41,17.53)
  L04_SIG1 w0.102: v1(68.41,17.53) 68.62,17.73 68.62,18.01 69.05,18.45 72.05,18.45 72.49,18 72.49,17.8 72.49,16.34 72.66,16.17 73.13,16.17 v1(73.44,16.48)
4_CLKGEN_REFCLK1P: length 11.6
  TOP w0.203: v1(69.27,17.53) 69.05,17.31 69.05,16.64 R241.2 ; R242.2 75.32,15.86 74.81,15.86 R244.1 74.25,15.86 73.68,15.86 v1(73.44,15.63)
  L04_SIG1 w0.102: v1(69.27,17.53) 69.19,17.45 69.01,17.45 68.86,17.6 68.86,17.91 69.15,18.2 71.95,18.2 72.25,17.9 72.25,16.24 72.56,15.93 73.2,15.93 73.44,15.69 v1(73.44,15.63)
4_CLKGEN_REFCLK2N: length 31.3
  TOP w0.203: v1(68.37,10.41) 68.58,10.62 68.58,13.35 68.55,13.37 68.55,13.38 R251.2 ; R227.2 78.6,22.25 78.6,22.63 R225.1 78.66,23.13 78.66,23.83 v1(78.83,24)
  L04_SIG1 w0.102: v1(78.83,24) 78.53,23.7 78.53,9.81 78.12,9.41 68.68,9.41 68.42,9.67 68.42,10.36 v1(68.37,10.41)
4_CLKGEN_REFCLK2P: length 31.3
  TOP w0.203: R226.2 78.21,22.25 78.21,22.63 R224.1 78.28,23.25 78.28,23.7 v1(77.98,24) ; R252.2 68.96,13.21 68.96,10.77 v1(69.31,10.41)
  L04_SIG1 w0.102: v1(69.31,10.41) 68.98,10.41 68.66,10.1 68.66,9.77 68.78,9.65 78.02,9.65 78.28,9.91 78.28,23.9 78.18,24 v1(77.98,24)
4_EEPROM_WP: length 1.6
  TOP w0.356: U25.7 R255.2
4_MCU_SCL: length 75.2
  TOP w0.356: R234.1 v1(87.23,18.08)
  L04_SIG1 w0.234: J15.B5 64.08,28.1 65.32,29.34 69.79,29.34 72.02,27.11 83.76,27.11 85.85,25.03 85.85,19.47 v1(87.23,18.08) 84.74,15.59 84.74,8.59 82.19,6.05 68.83,6.05 63.27,11.61 v1(60.34,11.61)
  BOTTOM w0.356: J22.2 v1(60.34,11.61)
4_MCU_SDA: length 43.3
  TOP w0.356: v1(73.87,19.85) 74.85,18.87 75.61,18.87 R233.1
  L04_SIG1 w0.234: v1(59.54,13.76) 60.07,14.29 64.9,14.29 65.28,13.91 67.48,13.91 67.85,13.54 71.14,13.54 71.96,12.72 75.54,12.72 75.78,12.96 75.78,17.94 v1(73.87,19.85) 70.17,23.55 63.61,23.55 63.08,24.07 J15.B6
  BOTTOM w0.356: J22.3 v1(59.54,13.76)
4_PCIE_CLKREQN: length 3
  TOP w0.356: R217.2 55.09,29.71 J15.B12
4_PCIE_PRSNT1N: length 50.7
  TOP w0.203: 52.04,28.53 52.08,28.5 52.08,26.1 51.08,25.1 51.08,21.6 50.09,20.62 50.09,19.13
  TOP w0.356: v1(61.87,31.78) 62.66,31.78 62.99,31.45 62.99,29.36 63.34,29.01 68.6,29.01 70.58,27.03 70.58,23.14 69.66,22.21 J15.A1 ; v1(51.05,30.86) R216.2 51.54,30.19 52.04,29.69 52.04,28.53 ; 50.09,19.13 50.09,18.88 49.58,18.36 47.6,18.36 46.15,16.92 46.15,16.31 v1(46.1,16.26) 45.6,15.76 R243.2
  L04_SIG1 w0.234: v1(61.87,31.78) 61.51,31.42 51.61,31.42 v1(51.05,30.86)
  BOTTOM w0.356: R243.2 45.6,15.76 v1(46.1,16.26)
4_PCIE_PRSNTA2N: length 21
  TOP w0.203: 50.09,28.53 J15.B17 48.92,23.55 47.73,23.55 47.09,22.91 47.09,21.64 46.08,20.62 46.08,19.13
  TOP w0.356: R216.1 R215.2 50.02,28.6 50.09,28.53 ; 46.08,19.13 44.5,17.55 44.5,14.71 v1(45.17,14.03)
  BOTTOM w0.356: v1(45.17,14.03) 45.14,14 J22.21
4_PCIE_PRSNTB2N: length 27.6
  TOP w0.356: v1(44.34,13.66) 39.36,18.64 34.97,18.64 31.35,22.26 31.35,24.43 32.49,25.58 34.4,25.58 35.27,24.71 J15.B31
  BOTTOM w0.356: J22.22 v1(44.34,13.66) R299.2 R298.1
4_PCIE_REFCLK_N: length 21.7
  TOP w0.203: R251.1 v1(67.61,14.44)
  L04_SIG1 w0.102: J15.A14 54.08,21.21 54.08,21.21 54.12,21.25 55.91,21.25 58.71,18.45 65.51,18.45 65.89,18.45 68.49,15.85 68.49,14.69 68.23,14.44 v1(67.61,14.44)
  BOTTOM w0.203: R251.1 v1(67.61,14.44)
4_PCIE_REFCLK_P: length 21.7
  TOP w0.203: R252.1 v1(70.07,14.44)
  L04_SIG1 w0.102: v1(70.07,14.44) 69.06,14.44 68.73,14.77 68.73,15.95 65.99,18.69 65.41,18.69 58.81,18.69 56.01,21.49 54.25,21.49 54.09,21.65 J15.A13
  BOTTOM w0.203: R252.1 v1(70.07,14.44)
4_PCIE_RESETN: length 32.6
  TOP w0.203: 56.21,28.53 56.21,25.44 54.85,24.07 54.85,22.85 56.18,21.51 57.39,21.51 J15.A11
  TOP w0.356: J14.2 56.09,49.19 56.21,49.07 56.21,28.53
4_PCIE_RST: length 3.4
  TOP w0.356: R247.1 56.2,14.49 56.31,14.6 U24.1 56.94,13.78 v1(57.01,13.72)
  BOTTOM w0.356: v1(57.01,13.72) 57.14,13.59 J22.6
4_PCIE_RXN0: length 34.1
  BOTTOM w0.224: J15.A17 50.09,18.61 arc(50.32,18.04) 50.89,17.81 61.83,17.81 arc(62.49,17.53) 62.77,16.86 62.77,12.7 arc(62.72,12.42) 62.56,12.18 60.71,10.34 arc(60.49,10.19) 60.22,10.13 55.79,10.13 arc(54.58,9.64) 54.08,8.43 54.08,7.66 arc(54.08,7.59) 54.06,7.53 arc(53.97,7.39) 53.94,7.24 J22.40
4_PCIE_RXN1: length 36.3
  BOTTOM w0.224: J15.A22 44.79,19.91 arc(44.69,19.44) 45.09,19.18 45.5,19.18 arc(45.64,19.12) 45.7,18.97 45.7,18.34 arc(45.57,18.02) 45.24,17.88 38.24,17.88 arc(35.4,16.71) 34.22,13.87 34.22,7.94 arc(34.34,7.33) 34.68,6.82 36.1,5.4 arc(37.31,4.6) 38.72,4.32 43.28,4.32 arc(43.88,4.57) 44.13,5.16 44.13,5.47 arc(44.14,5.55) 44.19,5.62 44.21,5.64 arc(44.31,5.78) 44.34,5.95 J22.52
4_PCIE_RXP0: length 34.1
  BOTTOM w0.224: J22.39 54.74,7.18 arc(54.71,7.33) 54.62,7.47 54.59,7.49 arc(54.5,7.63) 54.47,7.8 54.47,8.43 arc(54.85,9.37) 55.79,9.75 60.22,9.75 arc(60.64,9.84) 60.98,10.07 62.83,11.91 arc(63.07,12.27) 63.15,12.7 63.15,16.86 arc(62.76,17.8) 61.83,18.19 50.89,18.19 arc(50.59,18.31) 50.47,18.61 50.47,18.83 arc(50.55,19.02) 50.74,19.1 51.47,19.1 arc(52.02,19.66) 51.47,20.21 J15.A16
4_PCIE_RXP1: length 36.3
  BOTTOM w0.224: J22.53 43.54,6.03 arc(43.56,5.93) 43.61,5.85 arc(43.71,5.7) 43.75,5.52 43.75,5.16 arc(43.61,4.83) 43.28,4.7 38.72,4.7 arc(37.45,4.95) 36.37,5.67 arc(36.37,5.67) 36.37,5.67 34.95,7.09 arc(34.69,7.48) 34.6,7.94 34.6,13.87 arc(35.67,16.44) 38.24,17.5 45.45,17.5 arc(45.9,17.69) 46.09,18.14 J15.A21
4_PCIE_TCK: length 8.9
  TOP w0.203: 64.08,20.88 64.08,19.13
  TOP w0.356: TP25.1 65.39,15.54 64.58,15.54 64.08,16.04 64.08,19.13 ; J15.A5 64.08,20.88
4_PCIE_TDI: length 6.1
  TOP w0.356: TP24.1 63.08,15.94 J15.A6
4_PCIE_TDO: length 7.8
  TOP w0.203: 62.27,19.13 62.27,19.3 62.08,19.48 62.08,20.85
  TOP w0.356: J15.A7 62.08,20.85 ; 62.27,19.13 62.27,15.62 62.47,15.42 TP26.1
4_PCIE_TMS: length 5.5
  TOP w0.356: J15.A8 61.08,19.13 61.56,18.66 61.56,16.16 TP23.1
4_PCIE_TRSTN: length 5.4
  TOP w0.203: 60.08,27.45 60.08,26.11
  TOP w0.356: 60.08,26.11 J15.B9 ; TP22.1 59.29,28.24 60.08,27.45
4_PCIE_TXN0: length 68.6
  BOTTOM w0.224: J22.43 51.54,6.21 arc(51.57,6.04) 51.67,5.9 arc(51.75,5.78) 51.77,5.64 51.77,3.66 arc(52.12,2.83) 52.95,2.49 62.43,2.49 arc(63.67,2.73) 64.71,3.43 70.65,9.37 arc(71.57,10.75) 71.89,12.37 71.89,26.03 arc(70.81,28.64) 68.21,29.72 53.4,29.72 arc(52.99,29.65) 52.62,29.47 arc(52.23,29) 52.09,28.4 J15.B15
4_PCIE_TXN1: length 64.2
  BOTTOM w0.224: J15.B20 47.22,26.58 arc(47.33,25.99) 46.83,25.65 46.62,25.65 arc(46.24,25.81) 46.08,26.19 46.08,27.49 arc(46.22,27.81) 46.53,27.94 47.5,27.94 arc(47.64,28) 47.7,28.14 47.7,28.44 arc(47.52,28.9) 47.07,29.08 34.72,29.08 arc(31.65,27.81) 30.39,24.75 30.39,15.31 arc(30.56,14.45) 31.05,13.72 31.39,13.37 arc(32.25,12.09) 32.55,10.58 32.55,6.39 arc(33.7,3.61) 36.48,2.46 43.58,2.46 arc(45.4,3.22) 46.15,5.03 46.15,5.54 arc(46.12,5.65) 46.06,5.75 arc(45.97,5.89) 45.94,6.04 J22.50
4_PCIE_TXP0: length 68.7
  BOTTOM w0.224: J22.42 52.34,6.08 arc(52.31,5.96) 52.24,5.86 arc(52.18,5.76) 52.15,5.64 52.15,3.66 arc(52.39,3.1) 52.95,2.87 62.43,2.87 arc(63.52,3.09) 64.44,3.7 70.38,9.64 arc(71.22,10.89) 71.51,12.37 71.51,26.03 arc(70.54,28.37) 68.21,29.34 53.4,29.34 arc(53.11,29.29) 52.85,29.16 arc(52.6,28.86) 52.51,28.49 52.51,28.29 arc(52.57,28.13) 52.73,28.07 53.44,28.07 arc(53.89,27.88) 54.08,27.42 54.08,25.98 arc(54,25.79) 53.81,25.7 53.09,25.7 arc(52.71,25.96) 52.8,26.42 J15.B14
4_PCIE_TXP1: length 64.2
  BOTTOM w0.224: J22.49 46.74,5.98 arc(46.71,5.83) 46.62,5.7 arc(46.55,5.6) 46.53,5.48 46.53,5.03 arc(45.67,2.95) 43.58,2.08 36.48,2.08 arc(33.43,3.35) 32.16,6.39 32.16,10.58 arc(31.89,11.95) 31.12,13.1 30.78,13.45 arc(30.21,14.3) 30.01,15.31 30.01,24.75 arc(31.39,28.08) 34.72,29.46 47.07,29.46 arc(47.79,29.17) 48.09,28.44 J15.B19
4_PCIE_WAKEN: length 47.7
  TOP w0.203: J15.B11 57.13,25.66 57.13,28.53
  TOP w0.356: v1(31.95,17.02) 32.98,15.99 R311.2 ; R218.2 57.13,28.53
  L04_SIG1 w0.234: v1(31.95,17.02) 30.67,18.3 30.67,24.41 35.09,28.83 54.43,28.83 58.08,25.17 J15.B11
4_PCIE_WAKEN_3V3: length 19.9
  TOP w0.356: R311.1 34.62,14.3 35.74,13.17 38.27,13.17 40.05,11.4 40.05,11.16 44.27,6.93 48.4,6.93 v1(49.14,7.67)
  BOTTOM w0.254: J22.46 v1(49.14,7.67)
4_PORZ: length 76.7
  TOP w0.356: v1(51.54,14.78) 50.38,14.78 50,15.16 49.54,15.16 48.62,14.25 48.62,13.84 47.51,12.73 42.43,12.73 41.26,13.89 41.26,15.88 39.2,17.93 34.87,17.93 30.59,22.22 30.59,24.74 34.2,28.35 45.75,28.35 50.58,33.17 53.02,33.17 54.21,34.37 54.21,48.33 53.55,48.99 J14.1
  BOTTOM w0.356: v1(51.54,14.78) 52.34,13.99 J22.12
4_PORZ_OUT: length 82
  TOP w0.356: R248.1 88.08,14.91 88.44,15.27 88.44,21.26 84.88,24.82 73.91,24.82 71.37,22.28 71.37,10.01 70.02,8.66 66.98,8.66 62.63,13 58.72,13 57.89,13.83 U24.2 v1(57.89,15.8)
  L04_SIG1 w0.234: v1(37.94,13.73) 41.71,17.5 52.63,17.5 54.07,16.06 55.04,16.06 55.63,16.65 57.04,16.65 v1(57.89,15.8)
  BOTTOM w0.381: J22.30 v1(37.94,13.73)
4_REFCLK_IN0N: length 39.4
  L04_SIG1 w0.102: v1(66.77,12.59) 66.77,12.34 66.97,12.14 67.69,12.14 67.93,11.9 67.93,11.1 67.41,10.58 66.14,10.58 64.11,12.61 50.91,12.61 48.8,10.51 47.73,10.51 v1(47.38,10.15)
  BOTTOM w0.203: v1(66.77,12.59) 66.77,12.51 66.97,12.31 68.44,12.31 68.76,12.62 68.76,13.31 68.47,13.6 R306.2 ; v1(47.38,10.15) 47.1,10.44 41.33,10.44 39.33,8.43 39.33,7.22 39.54,7.01 J22.58
4_REFCLK_IN0P: length 39.5
  L04_SIG1 w0.102: v1(66.77,11.64) 67.03,11.9 67.59,11.9 67.69,11.8 67.69,11.2 67.31,10.82 66.24,10.82 64.21,12.85 50.81,12.85 48.7,10.75 47.73,10.75 v1(47.38,11.1)
  BOTTOM w0.203: v1(47.38,11.1) 47.1,10.82 41.17,10.82 38.95,8.59 38.95,7.22 38.74,7.01 J22.59 ; R305.2 69.14,13.39 69.14,12.46 68.6,11.92 67.05,11.92 v1(66.77,11.64)
4_REFCLK_OUT0N: length 29.2
  L04_SIG1 w0.102: v1(42.77,14.05) 42.46,14.36 42.46,15.08 42.73,15.35 52.87,15.35 53.28,14.94 61.62,14.94 63.49,16.8 65.7,16.8 65.8,16.7 65.8,16.52 65.61,16.34 v1(65.38,16.34)
  BOTTOM w0.203: v1(42.77,14.05) 42.53,13.82 42.53,13.28 42.74,13.07 J22.24 ; C224.2 66.47,16.31 66.16,16.62 65.67,16.62 v1(65.38,16.34)
4_REFCLK_OUT0P: length 28.6
  L04_SIG1 w0.102: v1(65.38,17.29) 65.13,17.04 63.39,17.04 61.52,15.18 53.38,15.18 52.97,15.59 45.76,15.59 42.63,15.59 42.22,15.18 42.22,14.36 v1(41.91,14.05)
  BOTTOM w0.203: v1(41.91,14.05) 42.15,13.82 42.15,13.28 41.94,13.07 J22.25 ; v1(65.38,17.29) 65.67,17 66.16,17 66.47,17.32 C223.2
4_RESETN: length 35.4
  TOP w0.203: 57.89,19.13 57.89,20.62 59.09,21.82 59.09,25.14 57.97,26.26
  TOP w0.356: J14.3 58.63,49.17 57.97,48.5 57.97,26.26 ; 57.89,19.13 57.89,17.95 U24.4
4_USB_CM_DM: length 4.9
  TOP w0.208: U20.3 27.09,51.73 v1(26.95,51.87) 27.17,52.09 27.17,53 27.01,53.17 J13.2
  BOTTOM w0.208: FL25.3 27.17,50.69 27.17,51.65 v1(26.95,51.87)
4_USB_CM_DP: length 4.8
  TOP w0.208: J13.3 27.66,53.17 27.5,53.02 27.5,52.09 v1(27.72,51.87) 27.59,51.73 U20.2
  BOTTOM w0.208: FL25.4 27.5,50.69 27.5,51.65 v1(27.72,51.87)
4_USB_DM: length 78.4
  L04_SIG1 w0.109: v1(26.95,46.91) 27.23,46.63 27.23,45.48 29.68,43.03 29.68,28.13 28.1,26.55 28.1,14.34 32.12,10.33 32.12,5.49 34.97,2.64 48.33,2.64 50.25,4.56 54.36,4.56 55.64,5.85 55.64,7.3 55.92,7.59 56.61,7.59 56.84,7.82 56.84,8.15 v1(57.13,8.43)
  BOTTOM w0.208: FL25.2 26.93,48.35 27.17,48.12 27.17,47.13 v1(26.95,46.91) ; v1(57.13,8.43) 56.9,8.21 56.9,7.24 57.14,7 J22.36
4_USB_DP: length 77.8
  L04_SIG1 w0.109: v1(27.72,46.91) 27.61,46.91 27.44,46.74 27.44,45.57 29.89,43.12 29.89,28.04 28.31,26.46 28.31,14.43 32.33,10.41 32.33,5.58 35.05,2.85 48.24,2.85 50.16,4.78 54.27,4.78 55.43,5.94 55.43,7.39 55.84,7.8 56.52,7.8 56.63,7.91 56.63,8.15 v1(56.35,8.43)
  BOTTOM w0.208: FL25.1 27.74,48.37 27.5,48.13 27.5,47.13 v1(27.72,46.91) ; v1(56.35,8.43) 56.57,8.21 56.57,7.19 56.34,6.96 J22.37
4_USB_DRV_VBUS: length 64.8
  TOP w0.356: v1(57.82,11.68) 57.82,11.66 56.57,10.41 52,10.41 50.45,8.86 43.09,8.86 40.58,11.38 40.58,12.8 36.51,16.87 34.43,16.87 28.56,22.74 28.56,24.78 33.5,29.72 42.5,29.72 44.05,31.27 R214.1 43.42,36.28 43.18,36.52 U21.4
  BOTTOM w0.381: v1(57.82,11.68) 57.94,11.79 J22.5
4_USB_ID: length 90.1
  TOP w0.356: J13.4 28.3,53.96 28.3,52.44 28.81,51.94 29.45,51.94 ; 29.45,51.94 29.45,51.44 28.94,50.93 U20.1 ; 29.45,51.94 34.4,51.94 J5.6 36.47,52.24 42.36,52.24 44.94,49.66 44.94,29.97 44,29.03 33.87,29.03 29.83,24.99 29.83,22.23 34.65,17.4 36.86,17.4 42.07,12.19 48.24,12.19 49.77,13.72 v1(49.77,14.61)
  BOTTOM w0.356: v1(49.77,14.61) 50.1,14.61 50.74,13.97 J22.14
4_USB_VBUS: length 78.9
  TOP w0.381: J5.1 36.56,47.24 33.38,47.24 30.3,50.33 U20.6
  TOP w0.457: J13.1 26.36,52.67 24.96,51.27 24.96,49.92 25.63,49.25 28.07,49.25
  L04_SIG1 w0.381: v1(48.34,4.97) 47.88,4.51 36.58,4.51 34.2,6.9 34.2,11.04 30.17,15.06 30.17,25.58 31.57,26.97 31.57,41.27 31.95,41.66 v1(37.19,41.66)
  BOTTOM w0.254: J22.47 v1(48.34,4.97)
4_VCC_1V8: length 112.6
  TOP w0.508: J23.3 27.88,10.19 27.88,12.32 28.72,13.16 31.57,13.16 33.16,11.57 33.16,10.13 42.4,0.89 86.51,0.89 89.71,4.09 89.71,28.5 88.18,30.02 v1(82.91,30.02)
  L04_SIG1 w0.508: v1(76.44,30.02) v1(77.45,30.02) v1(81.9,30.02) v1(82.91,30.02)
  BOTTOM w0.381: C226.1 J23.3
4_VCC_3V3: length 39
  TOP w0.254: C151.1 56.67,17.27 U24.5
  TOP w0.381: R213.1 v1(49.17,44.53) ; v1(31.62,18.34) 31.1,18.34 24.13,25.31 v1(24.13,25.53) C142.1 ; R221.2 v1(24.07,24.37) ; R219.1 v1(10.87,24.93)
  L04_SIG1 w0.381: v1(31.62,18.34) 52.85,18.34 v1(54.59,16.6)
  vias: v1(19.27,33.26) v1(19.27,31.99) v1(19.27,30.72) v1(19.27,29.45) v1(20.28,33.26) v1(20.28,31.99) v1(20.28,30.72) v1(20.28,29.45) v1(21.3,33.26) v1(21.3,31.99) v1(21.3,30.72) v1(21.3,29.45) v1(47.9,48.34) v1(47.9,47.07) v1(47.9,45.8) v1(47.9,44.53) v1(49.17,48.34) v1(49.17,47.07) v1(49.17,45.8) v1(50.44,48.34) v1(50.44,47.07) v1(50.44,45.8) v1(50.44,44.53)
4_VCC_5V: length 12.9
  TOP w0.254: R212.1 v1(42.71,45.14)
  TOP w0.508: 25.19,6.91 25.38,7.1 J23.8 ; 23.92,7.04 24.11,7.23 J23.10
  L04_SIG1 w0.508: J23.10 24.11,7.35 23.8,7.04 ; 25.32,6.78 25.38,6.85 J23.8
  BOTTOM w0.508: J23.10 24.11,7.1 24.05,7.04 ; 25.32,6.91 25.38,6.97 J23.8
  vias: v1(23.48,6.21) v1(23.48,5.19) v1(23.48,4.18) v1(24.49,6.21) v1(24.49,5.19) v1(24.49,4.18) v1(35.1,32.8) v1(35.1,31.88) v1(36.12,32.8) v1(36.12,31.88) v1(37.13,31.88) v1(38.15,31.88)
4_VCC_12V: length 9.9
  TOP w0.508: J23.7 25.38,11.73 ; J23.9 24.11,11.73
  L03_PWR w0.508: 25.45,11.61 25.38,11.54 J23.7 ; J23.9 24.11,11.42 23.67,11.86
  BOTTOM w0.508: 24.05,11.73 24.11,11.67 J23.9 ; J23.7 25.38,11.42 25.07,11.73
  vias: v1(17.51,19.8) v1(17.51,18.78) v1(17.51,17.77) v1(17.51,16.75) v1(18.52,19.8) v1(18.52,18.78) v1(18.52,17.77) v1(18.52,16.75) v1(19.54,19.8) v1(19.54,18.78) v1(19.54,17.77) v1(19.54,16.75) v1(23.22,13.45) v1(23.22,12.43) v1(24.24,13.45) v1(24.24,12.43) v1(25.26,13.45) v1(25.26,12.43)
4_VCC_FUN_3V3: length 16.9
  TOP w0.254: C160.1 56.01,6.7 U25.8 ; R230.1 v1(87.23,20.12) ; R250.1 75.41,14.17 74.85,14.17 74.45,13.77 v1(73.9,13.77) ; R231.1 v1(74.79,19.86) ; R235.1 75.29,17.7 v1(74.79,18.21) ; R236.1 v1(87.23,17.07)
  TOP w0.381: v1(47.65,13.76) 47.65,14.52 48.84,15.71 50.22,15.71 50.31,15.62 51.71,15.62 v1(52.14,16.05)
  BOTTOM w0.381: R300.1 R301.1 R302.1 52.35,16.05 v1(52.14,16.05)
  vias: v1(46.6,13.77) v1(58.02,4.52) v1(59.31,4.52) v1(73.52,8.81) v1(73.52,7.8) v1(84.82,7.54) v1(85.83,7.54)
4_VCC_PCIE_3V3: length 11.4
  TOP w0.356: R213.2 v1(49.17,39.7)
  TOP w0.381: R217.1 v1(55.1,32.28) ; R218.1 v1(57.13,32.26) ; R215.1 v1(50.02,30.91)
  TOP w0.508: J15.A10 59.08,18.97 C148.1 ; C136.1 60.99,28.63 61.08,28.53 J15.B8
  BOTTOM w0.356: R299.1 44.07,16.03 v1(43.43,16.03)
  vias: v1(47.9,39.7) v1(47.9,38.43) v1(47.9,37.16) v1(47.9,35.89) v1(49.17,38.43) v1(49.17,37.16) v1(49.17,35.89) v1(50.44,39.7) v1(50.44,38.43) v1(50.44,37.16) v1(50.44,35.89)
4_VCC_PCIE_12V: length 5.1
  TOP w0.356: J15.A2 67.59,19.71 C152.1 67.56,18.52 C149.1 ; R229.2 v1(24.66,20.35) ; C134.1 v1(68.63,31.29)
  vias: v1(22.12,17.81) v1(22.12,16.54) v1(22.12,15.27) v1(23.39,17.81) v1(23.39,16.54) v1(23.39,15.27) v1(24.66,21.62) v1(24.66,19.08) v1(24.66,17.81) v1(24.66,16.54) v1(24.66,15.27) v1(25.93,21.62) v1(25.93,20.35) v1(25.93,19.08) v1(25.93,17.81) v1(25.93,16.54) v1(25.93,15.27) v1(66.59,33.32) v1(66.59,32.31) v1(66.59,31.29) v1(67.61,33.32) v1(67.61,32.31) v1(67.61,31.29) v1(68.63,33.32) v1(68.63,32.31)
4_WKUP_SCL: length 11.8
  TOP w0.356: v1(59.23,5.51) 59.23,7.78 57.94,9.07 53.7,9.07 53.07,8.43 U25.6
  BOTTOM w0.356: v1(59.23,5.51) 59.54,5.82 J22.33
4_WKUP_SDA: length 12.5
  TOP w0.356: v1(59.79,8.23) 58.24,9.78 53.34,9.78 51.8,8.24 U25.5
  BOTTOM w0.356: J22.34 58.74,7.18 v1(59.79,8.23)
CDCI4_EEPROMSEL: length 3.7
  TOP w0.305: R250.2 v1(77.33,14.4) 78.23,15.3 U23.23
  BOTTOM w0.356: R250.2 v1(77.33,14.4)
CDCI4_OE1: length 3.7
  TOP w0.305: R235.2 v1(77.33,17.7) 78.23,16.8 U23.20
  BOTTOM w0.356: R235.2 v1(77.33,17.7)
CDCI4_OE2: length 5.2
  TOP w0.305: R233.2 77.26,18.85 78.81,17.3 U23.19
  TOP w0.356: R228.1 R231.2 R233.2
CDCI4_OE3: length 4.8
  TOP w0.305: R234.2 84.31,18.08 83.53,17.3 U23.12
  TOP w0.356: R230.2 R232.1 R234.2
CDCI4_OE4: length 3.6
  TOP w0.305: U23.11 84.55,16.8 84.82,17.07 R236.2
  TOP w0.356: R239.1 R236.2
CDCI4_REFSEL: length 1.8
  TOP w0.254: v1(81.45,13.13) 81.26,13.33 U23.4
  BOTTOM w0.356: R307.1 81.35,13.23 v1(81.45,13.13)
CDCI4_RST: length 3.7
  TOP w0.305: U23.8 84.04,15.3 84.44,14.91 R248.2
  TOP w0.356: R248.2 R253.1
CDCI4_XIN: length 9.2
  TOP w0.305: U23.1 79.76,11.9 R254.1
  TOP w0.356: Y6.3 78.52,7.12 77.69,7.95 77.69,9.5 77.97,9.78 79.27,9.78 79.58,10.09 C156.2 79.58,11.73 R254.1
CDCI4_XOUT: length 13.8
  TOP w0.305: v1(83.87,14.4) 83.47,14.8 U23.7 ; U23.2 80.26,11.9 R254.2
  TOP w0.356: TP27.1 83.87,13.2 v1(83.87,14.4) ; Y6.1 80.44,9.4 C157.2 80.44,11.73 R254.2 81.07,11.73 v1(81.1,11.71)
  L04_SIG1 w0.234: v1(83.87,14.4) 83.87,13.89 82.09,12.12 81.51,12.12 v1(81.1,11.71)
CDCI4_Y1N: length 2.6
  TOP w0.203: R238.1 76.96,16.56 77.28,16.24 78.15,16.24 78.21,16.3 U23.21
CDCI4_Y1P: length 2.6
  TOP w0.203: U23.22 78.21,15.8 78.15,15.86 77.28,15.86 76.96,15.54 R242.1
CDCI4_Y2N: length 4.2
  TOP w0.203: R227.1 78.91,20.61 78.6,20.29 78.6,19.89 78.93,19.56 79.65,19.56 80.2,19 80.2,18.64 80.26,18.58 U23.17
CDCI4_Y2P: length 4.2
  TOP w0.203: R226.1 77.9,20.61 78.21,20.29 78.21,19.74 78.77,19.18 79.49,19.18 79.82,18.85 79.82,18.67 79.76,18.61 U23.18
PWR_GOOD4: length 1.7
  TOP w0.279: R219.2 13.53,24.04 U22.14
N16880346: length 1.6
  TOP w0.356: R212.2 42.71,41.74 U21.5
N17084018: length 4.8
  TOP w0.203: R241.1 v1(70.11,15.5)
  BOTTOM w0.203: v1(70.11,15.5) 69.25,15.5 69.05,15.71 69.05,16.6 68.64,17 67.71,17 67.39,17.32 C223.1
N17084031: length 4.1
  TOP w0.203: R240.1 v1(67.61,15.5)
  BOTTOM w0.203: C224.1 67.39,16.31 67.71,16.62 68.48,16.62 68.67,16.44 68.67,15.71 68.46,15.5 v1(67.61,15.5)
N17117472: length 7.7
  TOP w0.279: 18.27,22.54 U22.7
  TOP w0.356: 18.27,22.54 21.86,22.54 R222.1 R221.1 22.52,24.4 C142.2
N17117476: length 2.8
  TOP w0.254: U22.12 15.23,26.09 15.43,26.29 15.73,25.99 U22.11
N17117528: length 1.1
  TOP w0.356: R220.2 20.21,23.39 C144.1
N17117540: length 1.3
  TOP w0.279: U22.1 R223.1
N17117546: length 2.1
  TOP w0.279: C140.1 17.18,26.2 16.73,25.75 U22.9
N17117564: length 1.5
  TOP w0.279: U22.13 14.73,25.29 C141.2

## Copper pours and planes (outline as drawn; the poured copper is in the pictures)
DGND4 on TOP (solid shape): 42.27,52.9 37.83,52.9 37.83,54.81 37.4,55.24 37.4,56.71 42.27,56.71
DGND4 on TOP: 77.9,28.42 77.9,27.81 75.99,27.81 75.54,27.36 75.21,27.36 75.13,27.43 75.13,28.75 75.26,28.88 75.51,28.88 75.97,28.42
DGND4 on TOP: 84.37,9.75 84.37,9.14 86.28,9.14 86.74,8.69 87.07,8.69 87.14,8.76 87.14,10.08 87.02,10.21 86.76,10.21 86.3,9.75
DGND4 on TOP: 16.84,22.92 16.81,22.95 13.43,22.95 13.25,23.13 12.42,23.13 12.42,23.63 16.81,23.63 16.84,23.66 18.77,23.66 18.77,24.63 19.5,24.63 19.5,22.92
DGND4 on TOP: 9.53,0.53 9.53,57.18 113.06,57.18 113.06,0.53 ; 7 cut-outs
DGND4 on TOP: 81.45,28.42 81.45,27.81 83.36,27.81 83.82,27.36 84.15,27.36 84.22,27.43 84.22,28.75 84.1,28.88 83.84,28.88 83.38,28.42
DGND4 on BOTTOM: 9.53,57.07 107.3,57.07 113.06,51.32 113.06,0.53 9.53,0.53
DGND4 on L02_GND1, L05_GND2: 9.51,0.51 9.51,57.58 24.35,57.58 24.35,56.47 25.28,55.54 26.21,56.47 26.21,57.58 29.1,57.58 29.1,56.47 30.03,55.54 30.96,56.47 30.96,57.58 113.08,57.58 113.08,0.51
DGND4 on L03_PWR: 63.61,34.94 63.61,57.07 112.57,57.07 112.57,1.16 89.75,1.16 89.75,24.98 73.16,24.98 73.16,34.94 ; 1 cut-out
DGND4 on L04_SIG1: 47.33,56.73 112.33,56.73 112.33,1.11 26.93,1.11 26.93,7.05 26.55,7.43 26.55,11.6 26.93,11.98 26.93,24.35 30.65,28.07 33.85,28.07 34.07,28.29 47.15,28.29 47.33,28.46 ; 1 cut-out
V3V3_VCO_CDCI4 on TOP (solid shape): 79.23,13.26 77.07,11.1 77.07,7.92 76.18,7.92 76.18,9.83 76.31,9.96 76.31,11.23 76.44,11.35 76.44,12.75 76.18,13 76.18,13.77 77.96,13.77 78.21,14.02 78.21,14.64 78.42,14.85 79.23,14.85
V3V3_VCO_CDCI4 on BOTTOM (solid shape): 77.96,11.73 76.31,11.73 76.31,13.64 77.96,13.64
VDD12_CDCI4 on TOP (solid shape): 78.34,27.1 79.36,27.1 79.48,26.97 79.48,25.96 76.44,25.96 76.44,27.36 78.09,27.36
VDD34_CDCI4 on TOP (solid shape): 82.91,25.96 79.99,25.96 79.99,27.1 80.88,27.1 81.14,27.36 82.91,27.36
(no net) on TOP: 37.83,52.9 37.83,54.81 37.4,55.24 37.4,56.71 42.27,56.71 42.27,52.9
(no net) on TOP: 39.73,34.03 39.73,37.08 39.86,37.21 41.64,37.21 41.89,36.96 41.89,32 39.99,32 39.99,33.78
(no net) on TOP: 16.87,28.29 17.23,27.93 23.76,27.93 23.76,33.57 17.41,33.57 16.87,33.04
(no net) on TOP: 76.18,7.92 76.18,9.83 76.31,9.96 76.31,11.23 76.44,11.35 76.44,12.75 76.18,13 76.18,13.77 77.96,13.77 78.21,14.02 78.21,14.78 78.34,14.91 79.23,14.91 79.23,13.26 77.07,11.1 77.07,7.92
(no net) on TOP: 79.99,27.1 79.99,25.96 82.91,25.96 82.91,27.36 81.14,27.36 80.88,27.1
(no net) on TOP: 23.53,9.7 22.58,10.66 17.53,10.66 15.43,12.77 15.43,17.9 15.5,17.97 15.5,20.64 15.66,20.79 15.66,21.96 19.92,21.96 19.92,21.95 21.34,21.95 21.85,21.44 21.85,19.19 21.29,18.63 21.29,14.85 21.65,14.49 25.64,14.49 25.95,14.18 25.95,9.7
(no net) on TOP: 76.18,30.28 77.71,30.28 77.71,29.01 76.18,29.01
(no net) on TOP: 38.46,33.02 38.46,30.73 34.67,30.73 34.67,33.02
(no net) on TOP: 81.64,30.28 83.17,30.28 83.17,29.01 81.64,29.01
(no net) on TOP: 36.64,39.93 39.48,39.93 40.62,41.07 41.77,41.07 41.77,45.85 41.72,45.89 41.72,48.14 39.98,49.89 34.54,49.89 33.4,51.03 28.4,51.03 27.89,50.52 27.89,48.97 29.62,47.24 36.2,47.24 36.56,46.88 36.56,40.01
(no net) on TOP: 76.44,27.36 78.09,27.36 78.34,27.1 79.36,27.1 79.48,26.97 79.48,25.96 76.44,25.96
(no net) on BOTTOM: 76.31,13.64 76.31,11.73 77.96,11.73 77.96,13.64
4_PCIE_PRSNT1N on TOP (solid shape): 69.55,22.33 69.6,22.21 69.55,22.09 68.8,21.5 68.04,22.21 68.8,22.92
4_PORZ on TOP (solid shape): 54.44,49.85 53.66,49.07 53.55,49.04 53.45,49.07 52.67,49.85 53.55,50.8
4_USB_ID on TOP (solid shape): 34.24,51.89 34.29,52.05 34.45,52.1 35.47,51.89 35.32,51.02 34.46,50.88
4_USB_ID on TOP (solid shape): 36.19,52.18 36.37,52.13 36.41,51.96 36.11,50.83 35.26,51.02 35.07,51.88
4_USB_VBUS on TOP (solid shape): 36.38,47.2 36.44,47.37 36.61,47.42 38.68,46.82 37.86,45.94 36.98,45.12
4_USB_VBUS on TOP (solid shape): outline of 165 points within 27.89,39.93 41.77,51.03
4_VCC_1V8 on TOP (solid shape): 77.71,29.01 76.18,29.01 76.18,30.28 77.71,30.28
4_VCC_1V8 on TOP (solid shape): 83.17,29.01 81.64,29.01 81.64,30.28 83.17,30.28
4_VCC_3V3 on TOP (solid shape): 23.76,27.93 17.23,27.93 16.87,28.29 16.87,33.04 17.41,33.57 23.76,33.57
4_VCC_3V3 on TOP: 53.81,18.24 53.81,14.63 57.96,14.63 57.96,18.24
4_VCC_3V3 on TOP: 46.27,48.69 46.27,42.48 52.14,42.48 52.14,48.69
4_VCC_3V3 on L03_PWR: 10.1,57.02 62.59,57.02 62.59,40.66 36.33,40.66 29.32,33.65 29.32,22.52 10.1,22.52
